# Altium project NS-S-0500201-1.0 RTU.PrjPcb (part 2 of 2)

## Sheet 10_HW_Component.SchDoc
size A3; SheetNumber: 9; SheetTotal: 9; Organization: Altium Limited; Address1: L3, 12a Rodborough Rd; Address2: Frenchs Forest; Address3: NSW; Address4: Australia 2086
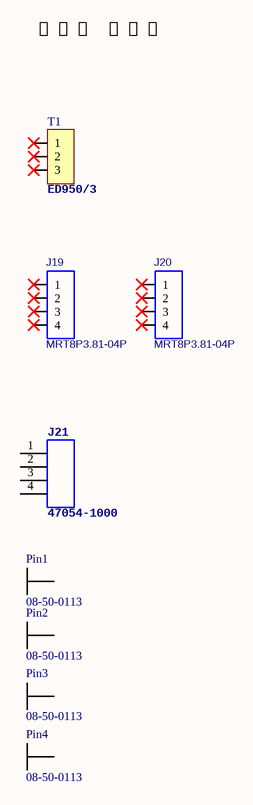
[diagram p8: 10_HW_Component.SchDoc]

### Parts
J19  MRT8P3.81-04P  (mechanical)
J20  MRT8P3.81-04P  (mechanical)
J21  47054-1000  (mechanical)
Pin1  08-50-0113  (mechanical)
Pin2  08-50-0113  (mechanical)
Pin3  08-50-0113  (mechanical)
Pin4  08-50-0113  (mechanical)
T1  ED950/3  (mechanical)

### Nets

Not connected (* = marked no-connect by the designer): J19 1* 2* 3* 4*; J20 1* 2* 3* 4*; J21 1 2 3 4; T1 1* 2* 3*

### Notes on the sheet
- 커넥터 상대물

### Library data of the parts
J19 J20 = MRT8P3.81-04P: TERM BLOCK PLUG 4POS STR 3.81mm(MRT9P3.81SQ-04P need); Maker: STELVIO
J21 = 47054-1000: Headers & Wire Housings KK .100" HSG 04P; PartNo.: 47053-1000; Maker: Molex
Pin1-Pin4 = 08-50-0113: Headers & Wire Housings KK TERM 22-30G / (Use with 47054-1000); Maker: Molex
T1 = ED950/3: TERM BLOCK PLUG 3POS STR 5MM; Maker: OnShore

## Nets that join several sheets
3V3: 3_Power_Boot (8 pins), 4_CM4_CONN (CPU_RUN.1 J3.78 PWR_ON.1 U4.5), 5_PERIPHERALS (10 pins), 6_USB2.0 (16 pins), 7_USB3.0 (22 pins), 8_CANFD (14 pins), 9_RS485 (8 pins)
5V: 3_Power_Boot (13 pins), 4_CM4_CONN (7 pins), 5_PERIPHERALS (C30.2 J8.2 U8.1), 6_USB2.0 (C35.2 U21.5), 7_USB3.0 (8 pins)
5V_ISO: 3_Power_Boot (5V_ISO.1 C16.2 L8.2), 8_CANFD (6 pins), 9_RS485 (8 pins)
DGND: 3_Power_Boot (31 pins), 4_CM4_CONN (53 pins), 5_PERIPHERALS (43 pins), 6_USB2.0 (34 pins), 7_USB3.0 (50 pins), 8_CANFD (22 pins), 9_RS485 (12 pins)
GND_ISO: 3_Power_Boot (C15.2 C16.1 DC2.3 R3.1), 8_CANFD (14 pins), 9_RS485 (16 pins)
CM4_3V3: 3_Power_Boot (R6.2 U1.10), 4_CM4_CONN (J3.84 J3.86)
DSI1_C_N: 4_CM4_CONN (J3.187), 5_PERIPHERALS (J6.5)
DSI1_C_P: 4_CM4_CONN (J3.189), 5_PERIPHERALS (J6.6)
DSI1_D0_N: 4_CM4_CONN (J3.175), 5_PERIPHERALS (J6.8)
DSI1_D0_P: 4_CM4_CONN (J3.177), 5_PERIPHERALS (J6.9)
DSI1_D1_N: 4_CM4_CONN (J3.181), 5_PERIPHERALS (J6.2)
DSI1_D1_P: 4_CM4_CONN (J3.183), 5_PERIPHERALS (J6.3)
EEPROM_nWP: 3_Power_Boot (J2.4), 4_CM4_CONN (J3.20)
Ethernet_nLED2: 4_CM4_CONN (J3.17), 5_PERIPHERALS (R22.2)
Ethernet_nLED3: 4_CM4_CONN (J3.15), 5_PERIPHERALS (R21.2)
Ethernet_Pair0_N: 4_CM4_CONN (J3.10), 5_PERIPHERALS (J10.10)
Ethernet_Pair0_P: 4_CM4_CONN (J3.12), 5_PERIPHERALS (J10.11)
Ethernet_Pair1_N: 4_CM4_CONN (J3.6), 5_PERIPHERALS (J10.5)
Ethernet_Pair1_P: 4_CM4_CONN (J3.4), 5_PERIPHERALS (J10.4)
Ethernet_Pair2_N: 4_CM4_CONN (J3.9), 5_PERIPHERALS (J10.2)
Ethernet_Pair2_P: 4_CM4_CONN (J3.11), 5_PERIPHERALS (J10.3)
Ethernet_Pair3_N: 4_CM4_CONN (J3.5), 5_PERIPHERALS (J10.9)
Ethernet_Pair3_P: 4_CM4_CONN (J3.3), 5_PERIPHERALS (J10.8)
GLOBAL_EN: 3_Power_Boot (J2.10 U2.4), 4_CM4_CONN (J3.99)
GPIO17: 3_Power_Boot (R11.2), 4_CM4_CONN (J3.50)
HDMI0_CEC: 4_CM4_CONN (J3.151), 5_PERIPHERALS (U11.9)
HDMI0_CLK_N: 4_CM4_CONN (J3.190), 5_PERIPHERALS (U10.10)
HDMI0_CLK_P: 4_CM4_CONN (J3.188), 5_PERIPHERALS (U10.9)
HDMI0_HOTPLUG: 4_CM4_CONN (J3.153), 5_PERIPHERALS (U11.14)
HDMI0_SCL: 4_CM4_CONN (J3.200), 5_PERIPHERALS (U11.11)
HDMI0_SDA: 4_CM4_CONN (J3.199), 5_PERIPHERALS (U11.12)
HDMI0_TX0_N: 4_CM4_CONN (J3.184), 5_PERIPHERALS (U10.7)
HDMI0_TX0_P: 4_CM4_CONN (J3.182), 5_PERIPHERALS (U10.6)
HDMI0_TX1_N: 4_CM4_CONN (J3.178), 5_PERIPHERALS (U9.10)
HDMI0_TX1_P: 4_CM4_CONN (J3.176), 5_PERIPHERALS (U9.9)
HDMI0_TX2_N: 4_CM4_CONN (J3.172), 5_PERIPHERALS (U9.7)
HDMI0_TX2_P: 4_CM4_CONN (J3.170), 5_PERIPHERALS (U9.6)
nEXTRST: 4_CM4_CONN (J3.100), 6_USB2.0 (U24.26)
nRPIBOOT: 3_Power_Boot (J2.2), 4_CM4_CONN (J3.93)
PCIe_CLK_N: 4_CM4_CONN (J3.112), 7_USB3.0 (U15.2)
PCIe_CLK_P: 4_CM4_CONN (J3.110), 7_USB3.0 (U15.1)
PCIe_nRST: 4_CM4_CONN (J3.109), 7_USB3.0 (U15.47)
PCIe_RX_N: 4_CM4_CONN (J3.118), 7_USB3.0 (C78.1)
PCIe_RX_P: 4_CM4_CONN (J3.116), 7_USB3.0 (C80.1)
PCIe_TX_N: 4_CM4_CONN (J3.124), 7_USB3.0 (U15.7)
PCIe_TX_P: 4_CM4_CONN (J3.122), 7_USB3.0 (U15.8)
RUN_PG: 3_Power_Boot (5 pins), 4_CM4_CONN (J3.92)
RXD0: 4_CM4_CONN (J3.51), 9_RS485 (C110.1 IC2.1 R45.1)
RXD5: 4_CM4_CONN (J3.28), 9_RS485 (C116.1 IC3.1 R50.1)
SCL0: 4_CM4_CONN (J3.80), 5_PERIPHERALS (J6.11)
SCL3: 3_Power_Boot (IC1.8 R8.1), 4_CM4_CONN (J3.34), 5_PERIPHERALS (U5.2)
SD1_CLK: 4_CM4_CONN (J3.46), 5_PERIPHERALS (J5.5)
SD1_CMD: 4_CM4_CONN (J3.47), 5_PERIPHERALS (J5.3)
SD1_DAT0: 4_CM4_CONN (J3.48), 5_PERIPHERALS (J5.7)
SD1_DAT1: 4_CM4_CONN (J3.41), 5_PERIPHERALS (J5.8)
SD1_DAT2: 4_CM4_CONN (J3.24), 5_PERIPHERALS (J5.1)
SD1_DAT3: 4_CM4_CONN (J3.45), 5_PERIPHERALS (J5.2)
SDA0: 4_CM4_CONN (J3.82), 5_PERIPHERALS (J6.12)
SDA3: 3_Power_Boot (IC1.7 R9.1), 4_CM4_CONN (J3.54), 5_PERIPHERALS (U5.1)
SPI0_CE0_N: 4_CM4_CONN (J3.39), 8_CANFD (U18.13)
SPI0_MISO: 4_CM4_CONN (J3.40), 8_CANFD (U18.12)
SPI0_MOSI: 4_CM4_CONN (J3.44), 8_CANFD (U18.11)
SPI0_SCLK: 4_CM4_CONN (J3.38), 8_CANFD (U18.10)
SPI6_CE0_N: 4_CM4_CONN (J3.49), 8_CANFD (U20.13)
SPI6_MISO: 4_CM4_CONN (J3.26), 8_CANFD (U20.12)
SPI6_MOSI: 4_CM4_CONN (J3.27), 8_CANFD (U20.11)
SPI6_SCLK: 4_CM4_CONN (J3.25), 8_CANFD (U20.10)
TXD0: 4_CM4_CONN (J3.55), 9_RS485 (C111.1 IC2.2 R44.2)
TXD5: 4_CM4_CONN (J3.31), 9_RS485 (C117.1 IC3.2 R49.2)
USB_N: 4_CM4_CONN (J3.103), 6_USB2.0 (U23.4)
USB_OTG_ID: 4_CM4_CONN (J3.101), 6_USB2.0 (R54.1 R55.2 U23.2)
USB_P: 4_CM4_CONN (J3.105), 6_USB2.0 (U23.3)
